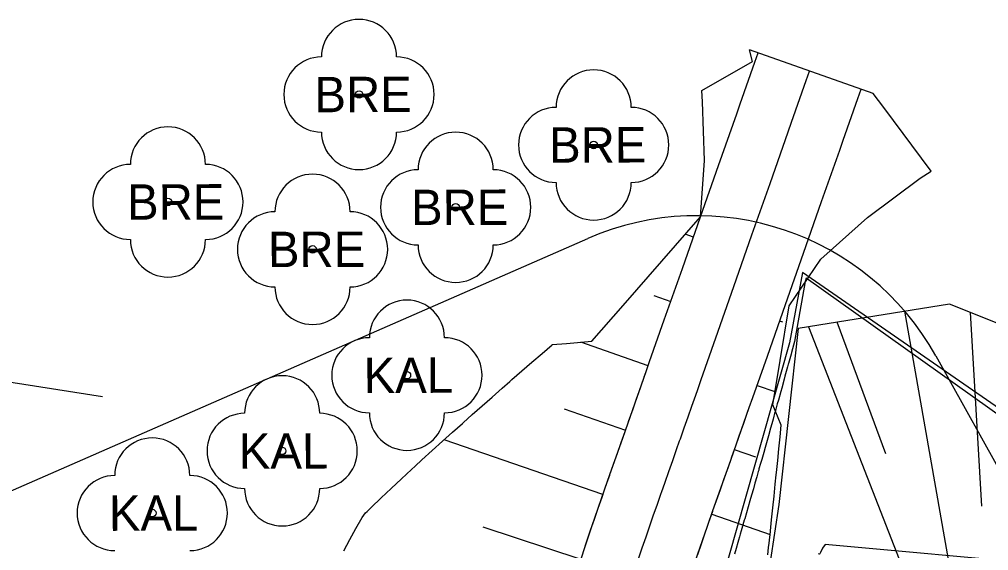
# Model space of a CAD drawing. Extents: x -564037 to -563722, y -1163561 to -1163412.
# Drawn here: x -563938.1 to -563920.35, y -1163476.6 to -1163466.87 of the extents above; entities that cross this region are included whole.
import ezdxf

# ---------------------------------------------------------------- set-up
doc = ezdxf.new("R2010")
doc.units = 0
for name, color, linetype in [('5', 7, 'Continuous'), ('Default', 7, 'Continuous'), ('Line', 7, 'Continuous'), ('Vrstva 1', 7, 'Continuous'), ('Vrstva 2', 7, 'Continuous')]:
    doc.layers.add(name, color=color, linetype=linetype)

msp = doc.modelspace()

# ---------------------------------------------------------------- linework, layer by layer
for points in [[(-563924.676, -1163467.645), (-563924.732, -1163467.431)], [(-563924.676, -1163467.645), (-563924.732, -1163467.431)], [(-563924.008, -1163472.119), (-563923.43, -1163471.262), (-563922.574, -1163470.503), (-563921.61, -1163469.782), (-563921.407, -1163469.65), (-563922.274, -1163468.488), (-563922.471, -1163468.226), (-563924.732, -1163467.431)], [(-563927.78, -1163476.635), (-563927.712, -1163476.432), (-563927.643, -1163476.229), (-563927.62, -1163476.16), (-563927.574, -1163476.026), (-563927.504, -1163475.823), (-563927.434, -1163475.621), (-563927.388, -1163475.491), (-563927.363, -1163475.419), (-563927.293, -1163475.22), (-563927.289, -1163475.206), (-563927.223, -1163475.02), (-563927.153, -1163474.82), (-563927.083, -1163474.621), (-563927.013, -1163474.421), (-563926.957, -1163474.263), (-563926.943, -1163474.222), (-563926.872, -1163474.022), (-563926.802, -1163473.822), (-563926.732, -1163473.623), (-563926.662, -1163473.423), (-563926.662, -1163473.422), (-563926.626, -1163473.319), (-563926.562, -1163473.139), (-563926.294, -1163472.376), (-563925.963, -1163471.432), (-563925.631, -1163470.489), (-563925.3, -1163469.545), (-563924.968, -1163468.602), (-563924.905, -1163468.421), (-563924.637, -1163467.658), (-563924.576, -1163467.486)], [(-563927.78, -1163476.635), (-563927.712, -1163476.432), (-563927.643, -1163476.229), (-563927.62, -1163476.16), (-563927.574, -1163476.026), (-563927.504, -1163475.823), (-563927.434, -1163475.621), (-563927.388, -1163475.491), (-563927.363, -1163475.419), (-563927.293, -1163475.22), (-563927.289, -1163475.206), (-563927.223, -1163475.02), (-563927.153, -1163474.82), (-563927.083, -1163474.621), (-563927.013, -1163474.421), (-563926.957, -1163474.263), (-563926.943, -1163474.222), (-563926.872, -1163474.022), (-563926.802, -1163473.822), (-563926.732, -1163473.623), (-563926.662, -1163473.423), (-563926.662, -1163473.422), (-563926.626, -1163473.319), (-563926.562, -1163473.139), (-563926.294, -1163472.376), (-563925.963, -1163471.432), (-563925.631, -1163470.489), (-563925.3, -1163469.545), (-563924.968, -1163468.602), (-563924.905, -1163468.421), (-563924.637, -1163467.658), (-563924.576, -1163467.486)], [(-563925.631, -1163470.489), (-563925.556, -1163469.455), (-563925.595, -1163468.382), (-563925.604, -1163468.176), (-563924.676, -1163467.645)], [(-563925.631, -1163470.489), (-563925.556, -1163469.455), (-563925.595, -1163468.382), (-563925.604, -1163468.176), (-563924.676, -1163467.645)], [(-563926.764, -1163476.751), (-563926.697, -1163476.55), (-563926.673, -1163476.482), (-563926.628, -1163476.35), (-563926.559, -1163476.15), (-563926.49, -1163475.95), (-563926.445, -1163475.822), (-563926.42, -1163475.751), (-563926.35, -1163475.551), (-563926.345, -1163475.538), (-563926.28, -1163475.351), (-563926.209, -1163475.152), (-563926.139, -1163474.952), (-563926.069, -1163474.753), (-563926.014, -1163474.594), (-563925.999, -1163474.553), (-563925.929, -1163474.353), (-563925.859, -1163474.154), (-563925.789, -1163473.954), (-563925.719, -1163473.755), (-563925.718, -1163473.753), (-563925.682, -1163473.651), (-563925.619, -1163473.47), (-563925.351, -1163472.707), (-563925.019, -1163471.764), (-563924.688, -1163470.82), (-563924.356, -1163469.877), (-563924.025, -1163468.933), (-563923.962, -1163468.753), (-563923.694, -1163467.99), (-563923.633, -1163467.817)], [(-563925.682, -1163476.675), (-563925.614, -1163476.477), (-563925.546, -1163476.28), (-563925.502, -1163476.154), (-563925.476, -1163476.082), (-563925.406, -1163475.882), (-563925.402, -1163475.869), (-563925.336, -1163475.683), (-563925.266, -1163475.483), (-563925.196, -1163475.284), (-563925.126, -1163475.084), (-563925.07, -1163474.926), (-563925.056, -1163474.884), (-563924.986, -1163474.685), (-563924.915, -1163474.485), (-563924.845, -1163474.286), (-563924.775, -1163474.086), (-563924.775, -1163474.084), (-563924.739, -1163473.982), (-563924.675, -1163473.801), (-563924.407, -1163473.039), (-563924.076, -1163472.095), (-563923.744, -1163471.152), (-563923.413, -1163470.208), (-563923.082, -1163469.265), (-563923.018, -1163469.084), (-563922.75, -1163468.321), (-563922.689, -1163468.149)], [(-563925.682, -1163476.675), (-563925.614, -1163476.477), (-563925.546, -1163476.28), (-563925.502, -1163476.154), (-563925.476, -1163476.082), (-563925.406, -1163475.882), (-563925.402, -1163475.869), (-563925.336, -1163475.683), (-563925.266, -1163475.483), (-563925.196, -1163475.284), (-563925.126, -1163475.084), (-563925.07, -1163474.926), (-563925.056, -1163474.884), (-563924.986, -1163474.685), (-563924.915, -1163474.485), (-563924.845, -1163474.286), (-563924.775, -1163474.086), (-563924.775, -1163474.084), (-563924.739, -1163473.982), (-563924.675, -1163473.801), (-563924.407, -1163473.039), (-563924.076, -1163472.095), (-563923.744, -1163471.152), (-563923.413, -1163470.208), (-563923.082, -1163469.265), (-563923.018, -1163469.084), (-563922.75, -1163468.321), (-563922.689, -1163468.149)], [(-563924.008, -1163472.119), (-563923.43, -1163471.262), (-563922.574, -1163470.503), (-563921.61, -1163469.782), (-563921.407, -1163469.65), (-563922.274, -1163468.488), (-563922.471, -1163468.226)], [(-563932.161, -1163476.605), (-563932.051, -1163476.402), (-563931.941, -1163476.2), (-563931.829, -1163475.999), (-563931.764, -1163475.913), (-563931.734, -1163475.884), (-563931.663, -1163475.815), (-563931.479, -1163475.639), (-563931.294, -1163475.463), (-563931.108, -1163475.289), (-563930.921, -1163475.115), (-563930.858, -1163475.056), (-563930.734, -1163474.942), (-563930.546, -1163474.77), (-563930.357, -1163474.6), (-563930.235, -1163474.491), (-563930.17, -1163474.433), (-563929.99, -1163474.272), (-563929.978, -1163474.262), (-563929.809, -1163474.111), (-563929.629, -1163473.951), (-563929.447, -1163473.79), (-563929.265, -1163473.63), (-563929.121, -1163473.503), (-563929.083, -1163473.47), (-563928.9, -1163473.31), (-563928.717, -1163473.15), (-563928.533, -1163472.99), (-563928.348, -1163472.831), (-563928.347, -1163472.83), (-563928.083, -1163472.807), (-563927.618, -1163472.768), (-563927.046, -1163472.112), (-563926.339, -1163471.3), (-563925.631, -1163470.489)], [(-563923.696, -1163471.61), (-563923.713, -1163471.675), (-563923.91, -1163472.772), (-563923.964, -1163472.971), (-563923.973, -1163473.003), (-563924.021, -1163473.177), (-563924.024, -1163473.19), (-563924.037, -1163473.235), (-563924.084, -1163473.408), (-563924.099, -1163473.463), (-563924.144, -1163473.626), (-563924.162, -1163473.689), (-563924.205, -1163473.844), (-563924.224, -1163473.915), (-563924.265, -1163474.063), (-563924.273, -1163474.091), (-563924.288, -1163474.143), (-563924.302, -1163474.193), (-563924.326, -1163474.281), (-563924.349, -1163474.362), (-563924.387, -1163474.498), (-563924.412, -1163474.584), (-563924.449, -1163474.716), (-563924.474, -1163474.806), (-563924.51, -1163474.934), (-563924.532, -1163475.009), (-563924.56, -1163475.107), (-563924.565, -1163475.127), (-563924.572, -1163475.152), (-563924.6, -1163475.249), (-563924.634, -1163475.369), (-563924.663, -1163475.469), (-563924.697, -1163475.587), (-563924.726, -1163475.69), (-563924.759, -1163475.804), (-563924.79, -1163475.91), (-563924.822, -1163476.021), (-563924.829, -1163476.046), (-563924.853, -1163476.129), (-563924.861, -1163476.154), (-563924.885, -1163476.239), (-563924.903, -1163476.3), (-563924.917, -1163476.348), (-563924.935, -1163476.409), (-563924.948, -1163476.454), (-563924.98, -1163476.565), (-563925.009, -1163476.666)], [(-563912.506, -1163487.699), (-563911.986, -1163484.484), (-563911.574, -1163482.655), (-563911.953, -1163481.832), (-563913.535, -1163479.514), (-563916.332, -1163476.565), (-563917.329, -1163476.066), (-563918.514, -1163475.302), (-563923.696, -1163471.61)], [(-563936.58, -1163473.788), (-563948.11, -1163471.977), (-563953.964, -1163474.44)], [(-563924.398, -1163476.681), (-563924.384, -1163476.546), (-563924.375, -1163476.469), (-563924.352, -1163476.253), (-563924.351, -1163476.238), (-563924.329, -1163476.037), (-563924.306, -1163475.82), (-563924.284, -1163475.604), (-563924.261, -1163475.388), (-563924.244, -1163475.216), (-563924.239, -1163475.171), (-563924.217, -1163474.955), (-563924.196, -1163474.738), (-563924.174, -1163474.521), (-563924.153, -1163474.305), (-563924.153, -1163474.303), (-563924.209, -1163474.168), (-563924.309, -1163473.93), (-563924.174, -1163473.121), (-563924.008, -1163472.119)], [(-563924.398, -1163476.681), (-563924.384, -1163476.546), (-563924.375, -1163476.469), (-563924.352, -1163476.253), (-563924.351, -1163476.238), (-563924.329, -1163476.037), (-563924.306, -1163475.82), (-563924.284, -1163475.604), (-563924.261, -1163475.388), (-563924.244, -1163475.216), (-563924.239, -1163475.171), (-563924.217, -1163474.955), (-563924.196, -1163474.738), (-563924.174, -1163474.521), (-563924.153, -1163474.305), (-563924.153, -1163474.303), (-563924.209, -1163474.168), (-563924.309, -1163473.93), (-563924.174, -1163473.121), (-563924.008, -1163472.119)], [(-563927.94, -1163477.121), (-563927.62, -1163476.16), (-563927.388, -1163475.491), (-563927.289, -1163475.206), (-563927.055, -1163474.541), (-563926.957, -1163474.263), (-563926.626, -1163473.319), (-563926.562, -1163473.139)], [(-563925.727, -1163476.805), (-563925.502, -1163476.154), (-563925.402, -1163475.869), (-563925.168, -1163475.204), (-563925.07, -1163474.926), (-563924.739, -1163473.982), (-563924.675, -1163473.801)], [(-563914.71, -1163488.029), (-563913.607, -1163483.439), (-563913.607, -1163483.439), (-563915.027, -1163481.543), (-563915.494, -1163481.306), (-563916.26, -1163478.576), (-563916.853, -1163478.206), (-563918.564, -1163477.348), (-563919.324, -1163476.858), (-563923.345, -1163476.489), (-563923.394, -1163476.556), (-563923.434, -1163476.636), (-563923.448, -1163476.663), (-563923.45, -1163476.666), (-563923.468, -1163476.663)]]:
    msp.add_lwpolyline(points)
msp.add_lwpolyline([(-563930.469, -1163501.126), (-563927.863, -1163499.14), (-563925.937, -1163497.674), (-563921.059, -1163495.43), (-563912.613, -1163489.681), (-563911.421, -1163482.517), (-563913.266, -1163479.715), (-563914.137, -1163478.749), (-563916.309, -1163476.467), (-563917.281, -1163475.995), (-563923.761, -1163471.506), (-563924, -1163472.797), (-563925.435, -1163477.844), (-563927.008, -1163483.992), (-563927.659, -1163487.507), (-563928.13, -1163490.05), (-563928.806, -1163493.379), (-563930.34, -1163499.841), (-563930.622, -1163501.15)], close=True)
at = {"layer": '5'}
for p, q in [((-563952.243, -1163481.627), (-563927.696, -1163470.887)), ((-563921.324, -1163473.035), (-563903.913, -1163504.291))]:
    msp.add_line(p, q, dxfattribs=at)
msp.add_arc((-563925.692, -1163475.468), 5, 29.1194, 113.6313, dxfattribs=at)
at = {"layer": 'Default'}
msp.add_lwpolyline([(-563917.567, -1163473.488), (-563921.074, -1163472.087), (-563923.466, -1163472.472), (-563923.844, -1163472.533), (-563924.198, -1163475.76), (-563924.511, -1163477.861), (-563924.518, -1163477.902), (-563924.828, -1163479.981), (-563924.849, -1163480.121), (-563924.856, -1163480.165), (-563924.906, -1163480.403), (-563924.984, -1163480.77), (-563924.987, -1163480.784), (-563925.501, -1163483.223), (-563925.543, -1163483.419), (-563925.776, -1163484.521), (-563925.948, -1163485.244), (-563926.867, -1163489.1)], dxfattribs=at)
at = {"layer": 'Line'}
for p, q in [((-563925.762, -1163470.86), (-563925.91, -1163470.808)), ((-563926.485, -1163471.931), (-563926.176, -1163472.039)), ((-563921.893, -1163472.219), (-563920.362, -1163480.924)), ((-563924.122, -1163472.418), (-563924.182, -1163472.397)), ((-563920.479, -1163475.786), (-563920.684, -1163472.243)), ((-563923.655, -1163472.502), (-563920.364, -1163480.938)), ((-563922.236, -1163474.829), (-563923.127, -1163472.417)), ((-563926.59, -1163473.219), (-563927.824, -1163472.785)), ((-563924.596, -1163473.576), (-563924.269, -1163473.691)), ((-563928.125, -1163474.005), (-563927.004, -1163474.398)), ((-563927.417, -1163475.578), (-563930.327, -1163474.573)), ((-563924.618, -1163474.893), (-563925.01, -1163474.756)), ((-563925.424, -1163475.935), (-563924.358, -1163476.306)), ((-563929.614, -1163476.166), (-563927.821, -1163476.761))]:
    msp.add_line(p, q, dxfattribs=at)
at = {"layer": 'Vrstva 2'}
for centre in [(-563931.884, -1163468.247), (-563927.587, -1163469.171), (-563935.383, -1163470.216), (-563930.114, -1163470.314), (-563932.735, -1163471.084), (-563931.007, -1163473.39), (-563933.291, -1163474.776), (-563935.67, -1163475.915)]:
    msp.add_circle(centre, 0.0688, dxfattribs=at)
for centre, start, end in [((-563931.884, -1163467.559), 0, 180), ((-563932.572, -1163468.247), 90, 270), ((-563931.196, -1163468.247), 270, 90), ((-563927.587, -1163468.483), 0, 180), ((-563928.275, -1163469.171), 90, 270), ((-563926.899, -1163469.171), 270, 90), ((-563935.383, -1163469.528), 0, 180), ((-563931.884, -1163468.935), 180, 0), ((-563930.114, -1163469.626), 0, 180), ((-563936.071, -1163470.216), 90, 270), ((-563934.695, -1163470.216), 270, 90), ((-563932.735, -1163470.396), 0, 180), ((-563930.802, -1163470.314), 90, 270), ((-563929.426, -1163470.314), 270, 90), ((-563927.587, -1163469.859), 180, 0), ((-563933.423, -1163471.084), 90, 270), ((-563932.047, -1163471.084), 270, 90), ((-563935.383, -1163470.904), 180, 0), ((-563930.114, -1163471.002), 180, 0), ((-563932.735, -1163471.772), 180, 0), ((-563931.007, -1163472.702), 0, 180), ((-563931.695, -1163473.39), 90, 270), ((-563930.319, -1163473.39), 270, 90), ((-563933.291, -1163474.088), 0, 180), ((-563933.979, -1163474.776), 90, 270), ((-563932.603, -1163474.776), 270, 90), ((-563931.007, -1163474.078), 180, 0), ((-563935.67, -1163475.227), 0, 180), ((-563936.358, -1163475.915), 90, 270), ((-563934.982, -1163475.915), 270, 90), ((-563933.291, -1163475.464), 180, 0)]:
    msp.add_arc(centre, 0.688, start, end, dxfattribs=at)

# ---------------------------------------------------------------- texts
at = {"layer": 'Vrstva 1'}
for s, p in [('BRE', (-563932.699, -1163468.573)), ('BRE', (-563928.402, -1163469.497)), ('BRE', (-563936.13, -1163470.542)), ('BRE', (-563930.93, -1163470.64)), ('BRE', (-563933.551, -1163471.41)), ('KAL', (-563931.799, -1163473.716)), ('KAL', (-563934.084, -1163475.103)), ('KAL', (-563936.463, -1163476.241))]:
    msp.add_text(s, height=0.648, rotation=0.1546, dxfattribs=at).set_placement(p)

doc.saveas('drawing.dxf')
